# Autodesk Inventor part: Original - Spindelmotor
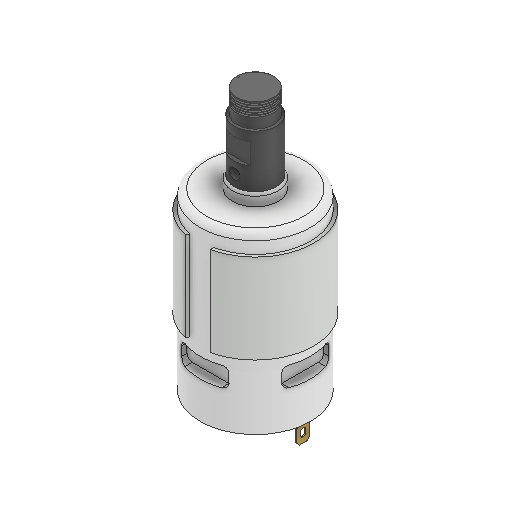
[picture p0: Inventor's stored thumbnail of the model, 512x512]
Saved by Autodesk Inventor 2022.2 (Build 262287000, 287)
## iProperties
Created: 2024-09
Part Number: Original - Spindelmotor
Material: Generico
Document SubType Name: Modeling
Designer: 18907419
Density: 1 g/cm^3
Appearance: Default
Author: 18907419
Revision Number: ANY
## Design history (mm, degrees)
feature "Aufsatz-Linear austragen3" [Gewinde]
feature "Schnitt-Linear austragen7" [Gewinde]
feature "Aufsatz-Linear austragen7[1]" [Gewinde]
feature "Aufsatz-Linear austragen7[2]" [Gewinde]
feature "Aufsatz-Linear austragen8" [Gewinde]
feature "Aufsatz-Linear austragen9" [Gewinde]
feature "Aufsatz-Linear austragen10[1]" [Gewinde]
feature "Aufsatz-Linear austragen10[2]" [Gewinde]
feature "Aufsatz-Linear austragen10[3]" [Gewinde]
feature "Aufsatz-Linear austragen10[5]" [Gewinde]
feature "Aufsatz-Linear austragen10[6]" [Gewinde]
feature "Aufsatz-Linear austragen10[7]" [Gewinde]
feature "Aufsatz-Linear austragen10[8]" [Gewinde]
feature "Schnitt-Linear austragen8" [Gewinde]
feature "Gewinde1"
node "Solido1"
node "Solido2"
node "Solido3"
node "Solido4"
node "Solido5"
node "Solido6"
node "Solido7"
node "Solido8"
node "Solido9"
node "Solido10"
node "Solido11"
node "Solido12"
node "Solido13"
node "Solido14"
node "Solido15"
